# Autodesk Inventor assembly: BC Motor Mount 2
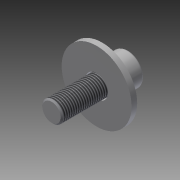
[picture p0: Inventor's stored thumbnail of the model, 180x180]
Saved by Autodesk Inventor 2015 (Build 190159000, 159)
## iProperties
Created: 2007-02
Part Number: BC Motor Mount 2
Document SubType Name: Assembly
Designer: Autodesk, Inc.
Mass: 40.8056 g
Surface Area: 39.4938 cm^2
Volume: 5.19155 cm^3
Density: 7.86 g/cm^3
ClientObjectVersion: 1
Author: Autodesk, Inc.
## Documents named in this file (4)
- C:\Users\Public\Documents\Autodesk\Inventor 2015\Samples\Models\Assemblies\Blower\Blower\Design Accelerator\BC Motor Mount 11.iam
- C:\Users\Public\Documents\Autodesk\Inventor 2015\Samples\Standard Parts\en-US\ANSI B18.22.1\ANSI B18.22.1 - 3_8 - wide - Type B.ipt
- C:\Users\Public\Documents\Autodesk\Inventor 2015\Samples\Standard Parts\en-US\ANSI B18.21.1\ANSI B18.21.1 - 0.375.ipt
- C:\Users\Public\Documents\Autodesk\Inventor 2015\Samples\Standard Parts\en-US\ANSI B18.3(13)\ANSI B18.3 - 3_8-24 UNF - 1(22).ipt
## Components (3 placed, 3 different names)
1. ANSI B18.22.1 - 3/8 - wide - Type B:1
2. ANSI B18.21.1 - 0.375:2
3. ANSI B18.3 - 3/8-24 UNF - 1:3
